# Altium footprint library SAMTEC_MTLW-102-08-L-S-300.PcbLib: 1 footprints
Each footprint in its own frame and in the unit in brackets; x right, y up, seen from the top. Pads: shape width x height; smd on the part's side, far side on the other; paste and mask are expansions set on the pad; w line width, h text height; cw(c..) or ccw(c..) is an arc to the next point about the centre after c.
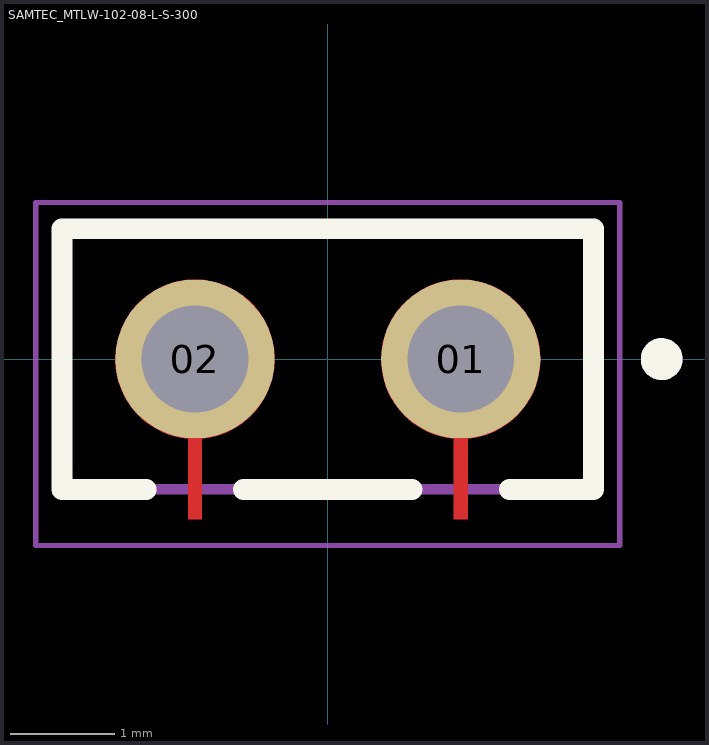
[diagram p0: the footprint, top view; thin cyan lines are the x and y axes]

## SAMTEC_MTLW-102-08-L-S-300 [mm]
pads (2):
  round 1.52 hole 1.02: 01(1.27,0) 02(-1.27,0)
Top Layer:
  region: 1.349,0.756 1.428,0.743 1.505,0.723 1.579,0.694 1.65,0.658 1.717,0.615 1.779,0.565 1.835,0.509 1.885,0.447 1.928,0.38 1.964,0.309 1.993,0.235 2.013,0.158 2.026,0.079 2.03,0 2.029,-0.038 2.026,-0.076 2.022,-0.113 2.015,-0.151 2.007,-0.187 1.997,-0.224 1.985,-0.259 1.971,-0.294 1.956,-0.329 1.939,-0.363 1.92,-0.395 1.9,-0.427 1.878,-0.458 1.855,-0.487 1.83,-0.516 1.804,-0.543 1.776,-0.569 1.747,-0.593 1.718,-0.616 1.687,-0.638 1.655,-0.658 1.622,-0.676 1.588,-0.692 1.553,-0.707 1.518,-0.721 1.482,-0.732 1.446,-0.742 1.409,-0.75 1.372,-0.756 1.335,-0.76 1.335,-1.53 1.205,-1.53 1.205,-0.76 1.168,-0.756 1.131,-0.75 1.094,-0.742 1.058,-0.732 1.022,-0.721 0.987,-0.707 0.952,-0.692 0.918,-0.676 0.885,-0.658 0.853,-0.638 0.822,-0.616 0.793,-0.593 0.764,-0.569 0.736,-0.543 0.71,-0.516 0.685,-0.487 0.662,-0.458 0.64,-0.427 0.62,-0.395 0.601,-0.363 0.584,-0.329 0.569,-0.294 0.555,-0.259 0.543,-0.224 0.533,-0.187 0.525,-0.151 0.518,-0.113 0.514,-0.076 0.511,-0.038 0.51,0 0.514,0.079 0.527,0.158 0.547,0.235 0.576,0.309 0.612,0.38 0.655,0.447 0.705,0.509 0.761,0.565 0.823,0.615 0.89,0.658 0.961,0.694 1.035,0.723 1.112,0.743 1.191,0.756 1.27,0.76
  region: -1.191,0.756 -1.112,0.743 -1.035,0.723 -0.961,0.694 -0.89,0.658 -0.823,0.615 -0.761,0.565 -0.705,0.509 -0.655,0.447 -0.612,0.38 -0.576,0.309 -0.547,0.235 -0.527,0.158 -0.514,0.079 -0.51,0 -0.511,-0.038 -0.514,-0.076 -0.518,-0.113 -0.525,-0.151 -0.533,-0.187 -0.543,-0.224 -0.555,-0.259 -0.569,-0.294 -0.584,-0.329 -0.601,-0.363 -0.62,-0.395 -0.64,-0.427 -0.662,-0.458 -0.685,-0.487 -0.71,-0.516 -0.736,-0.543 -0.764,-0.569 -0.793,-0.593 -0.822,-0.616 -0.853,-0.638 -0.885,-0.658 -0.918,-0.676 -0.952,-0.692 -0.987,-0.707 -1.022,-0.721 -1.058,-0.732 -1.094,-0.742 -1.131,-0.75 -1.168,-0.756 -1.205,-0.76 -1.205,-1.53 -1.335,-1.53 -1.335,-0.76 -1.372,-0.756 -1.409,-0.75 -1.446,-0.742 -1.482,-0.732 -1.518,-0.721 -1.553,-0.707 -1.588,-0.692 -1.622,-0.676 -1.655,-0.658 -1.687,-0.638 -1.718,-0.616 -1.747,-0.593 -1.776,-0.569 -1.804,-0.543 -1.83,-0.516 -1.855,-0.487 -1.878,-0.458 -1.9,-0.427 -1.92,-0.395 -1.939,-0.363 -1.956,-0.329 -1.971,-0.294 -1.985,-0.259 -1.997,-0.224 -2.007,-0.187 -2.015,-0.151 -2.022,-0.113 -2.026,-0.076 -2.029,-0.038 -2.03,0 -2.026,0.079 -2.013,0.158 -1.993,0.235 -1.964,0.309 -1.928,0.38 -1.885,0.447 -1.835,0.509 -1.779,0.565 -1.717,0.615 -1.65,0.658 -1.579,0.694 -1.505,0.723 -1.428,0.743 -1.349,0.756 -1.27,0.76
Top Overlay:
  circle w0.2: c3.19,0 r0.1
  lines w0.2: -1.735,-1.245 -2.54,-1.245 -2.54,1.245 2.54,1.245 2.54,-1.245 1.735,-1.245 ; -0.805,-1.245 0.805,-1.245
Top Paste:
  region: 2.35,-0.455 1.89,-0.455 1.525,-0.77 1.525,-1.53 1.015,-1.53 1.015,-0.77 0.65,-0.455 0.19,-0.455 0.19,1.085 2.35,1.085
  region: -0.19,-0.455 -0.65,-0.455 -1.015,-0.77 -1.015,-1.53 -1.525,-1.53 -1.525,-0.77 -1.89,-0.455 -2.35,-0.455 -2.35,1.085 -0.19,1.085
Top Solder:
  drawing of 2 lines, arcs and shapes, not listed
Mechanical 13:
  circle w0.2: c3.19,0 r0.1
  lines w0.1: -2.54,-1.245 -2.54,1.245 2.54,1.245 2.54,-1.245 -2.54,-1.245
Mechanical 15:
  lines w0.05: -2.79,-1.78 -2.79,1.495 2.79,1.495 2.79,-1.78 -2.79,-1.78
